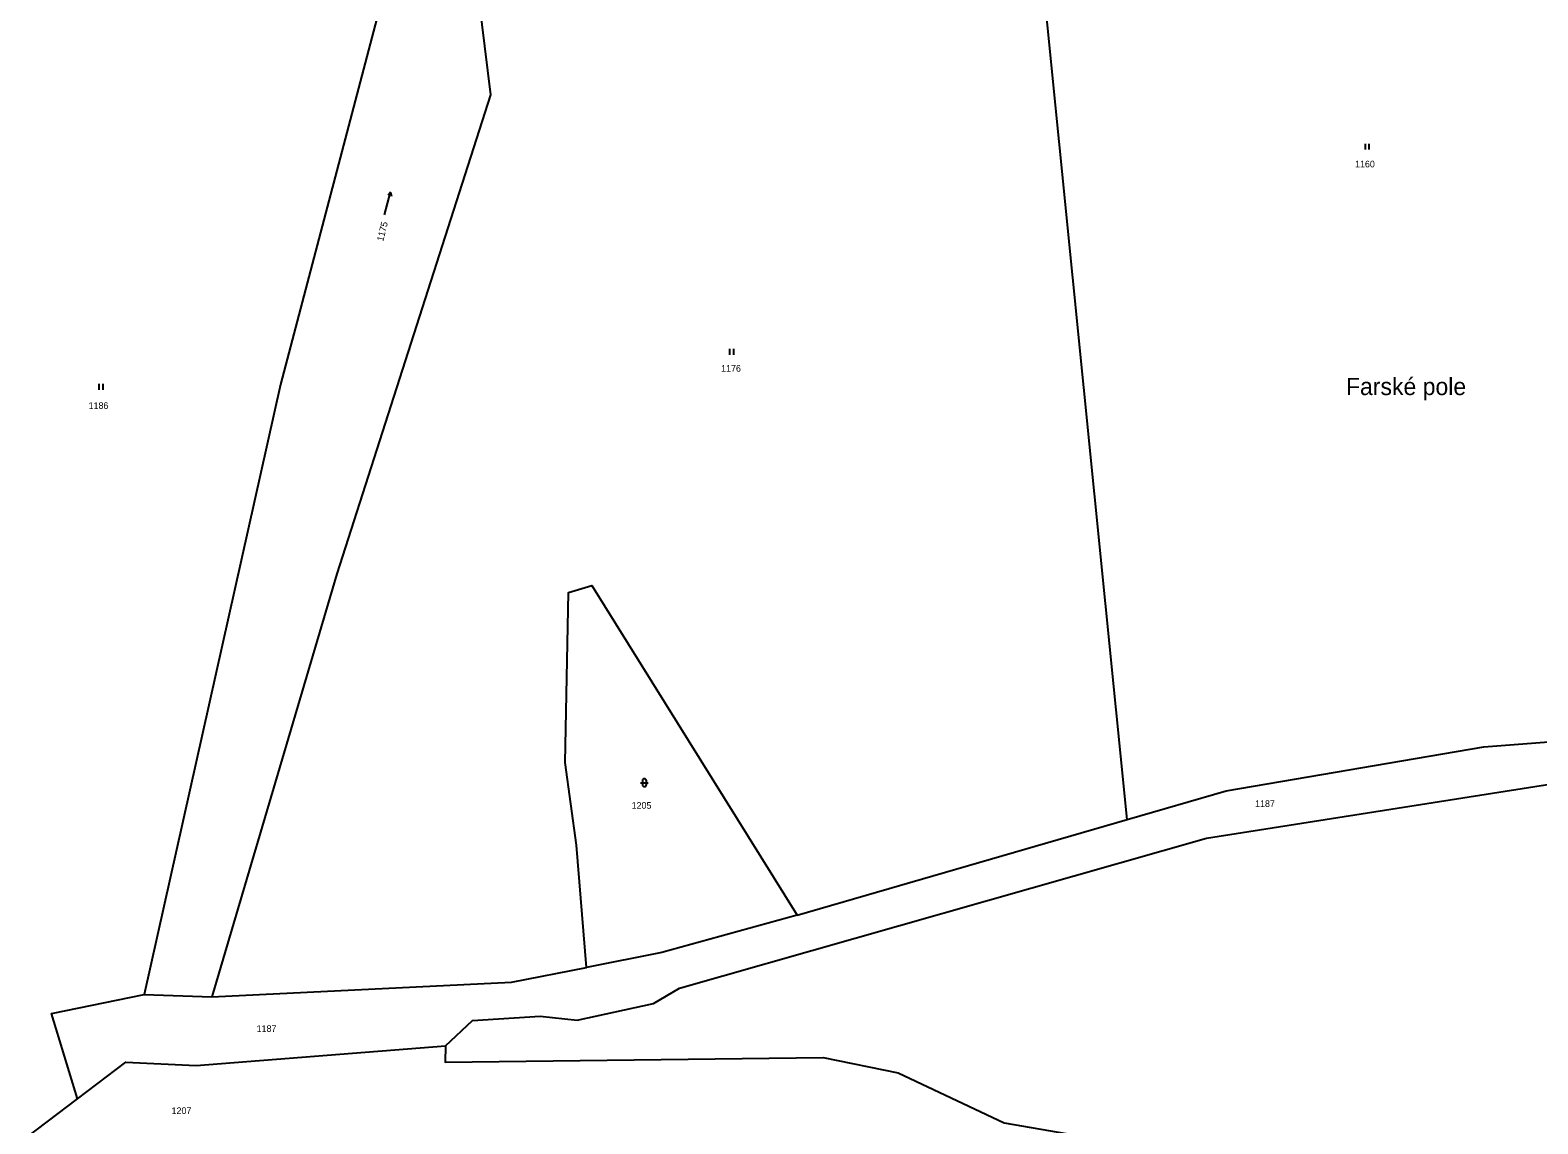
# Model space of a CAD drawing. Extents: x -520431 to -517205, y -1075927 to -1074013.
# Drawn here: x -518762.1 to -518376.5, y -1074599.9 to -1074320 of the extents above; entities that cross this region are included whole.
import ezdxf

# ---------------------------------------------------------------- set-up
doc = ezdxf.new("R2010")
doc.units = 0
for name, color, linetype in [('Hranice parcel', 7, 'Continuous'), ('Parcelní čísla', 7, 'Continuous'), ('Pop  PČ popisy', 7, 'Continuous'), ('Vrstva 54', 7, 'Continuous'), ('Značky kultur', 7, 'Continuous')]:
    doc.layers.add(name, color=color, linetype=linetype)

msp = doc.modelspace()

# ---------------------------------------------------------------- linework, layer by layer
at = {"layer": 'Hranice parcel'}
for p, q in [((-518565.95, -1074546.49), (-518481.5, -1074522)), ((-518732.98, -1074566.81), (-518715.65, -1074567.42))]:
    msp.add_line(p, q, dxfattribs=at)
for points in [[(-518481.5, -1074522), (-518495.4, -1074383.37), (-518509.31, -1074244.66)], [(-518648.11, -1074306.01), (-518644.39, -1074336.6), (-518683.65, -1074459.11), (-518715.65, -1074567.42)], [(-518671.34, -1074308.84), (-518698.04, -1074410.69), (-518732.98, -1074566.81)], [(-518619.84, -1074559.84), (-518622.34, -1074528.58), (-518625.3, -1074507.4), (-518624.44, -1074463.89), (-518618.42, -1074462.17), (-518565.95, -1074546.49)], [(-518655.84, -1074579.89), (-518648.98, -1074573.43), (-518631.66, -1074572.32), (-518622.17, -1074573.33), (-518602.63, -1074569.06), (-518596.04, -1074565.14), (-518461.23, -1074526.82), (-518363.68, -1074511.4), (-518266.46, -1074503.1), (-518258.1, -1074504.51), (-518238.38, -1074501.22), (-518230.79, -1074497.22), (-518209.23, -1074493.53), (-518198.06, -1074499.89)], [(-518481.5, -1074522), (-518456.23, -1074514.67), (-518390.24, -1074503.42), (-518340.51, -1074499.6)], [(-518565.95, -1074546.49), (-518600.57, -1074556.03), (-518619.84, -1074559.84)], [(-518715.65, -1074567.42), (-518639, -1074563.62), (-518619.84, -1074559.84)], [(-518750.03, -1074593.5), (-518756.63, -1074571.67), (-518732.98, -1074566.81)], [(-518750.03, -1074593.5), (-518737.61, -1074584.11), (-518719.63, -1074584.91), (-518655.84, -1074579.89)], [(-518655.84, -1074579.89), (-518655.92, -1074584.11), (-518559.23, -1074582.9), (-518540.09, -1074586.82), (-518512.95, -1074599.6), (-518319.13, -1074633.13), (-518291.79, -1074635.82), (-518220.74, -1074652.16), (-518160.18, -1074662.59)], [(-518845, -1074648.92), (-518778.64, -1074615.13), (-518750.03, -1074593.5)]]:
    msp.add_lwpolyline(points, dxfattribs=at)
at = {"layer": 'Vrstva 54'}
msp.add_lwpolyline([(-519036.69, -1074860.75), (-519005.51, -1074823.73), (-519003.22, -1074810.58), (-518976.94, -1074776.6), (-518961.58, -1074753.12), (-518933.45, -1074719.94), (-518892.49, -1074678.08), (-518873.27, -1074665.82), (-518860.87, -1074659.24), (-518845, -1074648.92), (-518778.64, -1074615.13), (-518750.03, -1074593.5), (-518737.61, -1074584.11), (-518719.63, -1074584.91), (-518655.84, -1074579.89), (-518655.92, -1074584.11), (-518655.92, -1074584.11), (-518559.23, -1074582.9), (-518540.09, -1074586.82), (-518512.95, -1074599.6), (-518319.13, -1074633.13)], dxfattribs=at)
at = {"layer": 'Značky kultur'}
for p, q in [((-518420.58, -1074350.58), (-518420.58, -1074349.08)), ((-518419.58, -1074350.58), (-518419.58, -1074349.08)), ((-518671.45, -1074367.26), (-518669.9, -1074361.47)), ((-518669.9, -1074361.47), (-518670.64, -1074362.28)), ((-518669.9, -1074361.47), (-518669.67, -1074362.54)), ((-518583.12, -1074403.08), (-518583.12, -1074401.58)), ((-518582.12, -1074403.08), (-518582.12, -1074401.58)), ((-518744.46, -1074412.06), (-518744.46, -1074410.56)), ((-518743.46, -1074412.06), (-518743.46, -1074410.56)), ((-518606, -1074512.59), (-518604, -1074512.59)), ((-518605.5, -1074512.09), (-518605.5, -1074513.09)), ((-518604.5, -1074513.09), (-518604.5, -1074512.09))]:
    msp.add_line(p, q, dxfattribs=at)
for centre, start, end in [((-518605, -1074512.09), 0, 180), ((-518605, -1074513.09), 180, 359.9879)]:
    msp.add_arc(centre, 0.5, start, end, dxfattribs=at)

# ---------------------------------------------------------------- texts
at = {"layer": 'Parcelní čísla'}
for s, p in [('1160', (-518423.22, -1074355.15)), ('1176', (-518585.37, -1074407.43)), ('1186', (-518747.15, -1074416.96)), ('1205', (-518608.26, -1074519.26)), ('1187', (-518448.79, -1074518.8)), ('1187', (-518704.18, -1074576.37)), ('1207', (-518725.94, -1074597.37))]:
    msp.add_text(s, height=1.7, dxfattribs=at).set_placement(p)
msp.add_text('1175', height=1.7, rotation=76, dxfattribs=at).set_placement((-518671.81, -1074374.19))
at = {"layer": 'Pop  PČ popisy'}
msp.add_text('Farské pole', height=4.4, dxfattribs=at).set_placement((-518425.54, -1074413.41))

doc.saveas('drawing.dxf')
